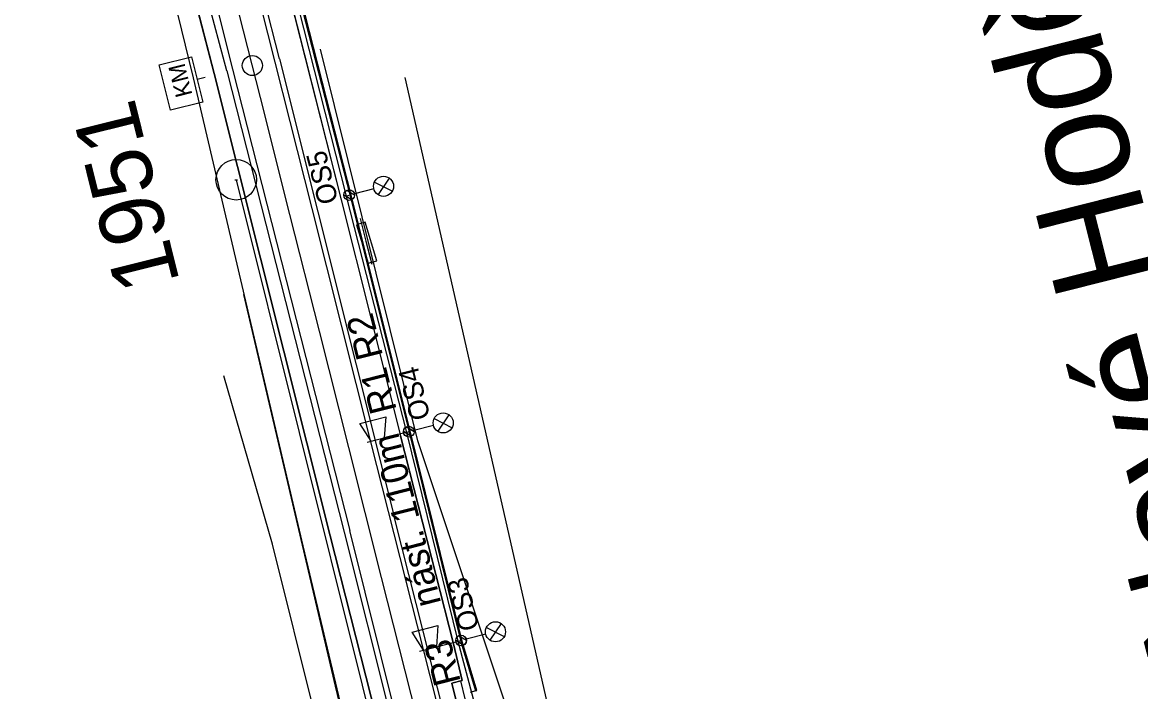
# Model space of a CAD drawing. Extents: x -754679 to -754173, y -1169241 to -1168288.
# Drawn here: x -754425.1 to -754341.7, y -1168914.1 to -1168864.2 of the extents above; entities that cross this region are included whole.
import ezdxf

# ---------------------------------------------------------------- set-up
doc = ezdxf.new("R2010")
doc.units = 0
for name, color, linetype in [('Vrstva 1', 7, 'Continuous'), ('Vrstva 14', 7, 'Continuous'), ('Vrstva 16', 7, 'Continuous'), ('Vrstva 2', 7, 'Continuous'), ('Vrstva 23', 7, 'Continuous'), ('Vrstva 25', 7, 'Continuous'), ('Vrstva 31', 7, 'Continuous'), ('Vrstva 33', 7, 'Continuous'), ('Vrstva 4', 7, 'Continuous'), ('Vrstva 43', 7, 'Continuous'), ('Vrstva 51', 7, 'Continuous'), ('Vrstva 53', 7, 'Continuous'), ('Vrstva 63', 7, 'Continuous'), ('Vrstva 7', 7, 'Continuous')]:
    doc.layers.add(name, color=color, linetype=linetype)

msp = doc.modelspace()

# ---------------------------------------------------------------- linework, layer by layer
at = {"layer": 'Vrstva 1'}
msp.add_line((-754409.148, -1168875.914), (-754409.148, -1168875.914), dxfattribs=at)
for points in [[(-754398.294, -1168905.574), (-754400.74, -1168895.891), (-754402.939, -1168887.198), (-754405.133, -1168878.507), (-754407.339, -1168869.778), (-754409.539, -1168861.07), (-754411.979, -1168851.401), (-754414.173, -1168842.726), (-754415.893, -1168835.935), (-754418.063, -1168827.345), (-754420.434, -1168817.966), (-754422.091, -1168811.412)], [(-754384.656, -1168959.571), (-754385.936, -1168954.491), (-754386.734, -1168951.322), (-754387.865, -1168946.893), (-754387.928, -1168946.598), (-754389.016, -1168942.293), (-754391.2, -1168933.67), (-754393.647, -1168923.979), (-754396.084, -1168914.315), (-754398.294, -1168905.574)]]:
    msp.add_lwpolyline(points, dxfattribs=at)
at = {"layer": 'Vrstva 14'}
for p, q in [((-754405.698, -1168860.083), (-754401.304, -1168877.422)), ((-754401.304, -1168877.422), (-754396.888, -1168895.004)), ((-754392.927, -1168910.532), (-754396.888, -1168895.004)), ((-754392.287, -1168913.272), (-754392.927, -1168910.532)), ((-754393.063, -1168913.475), (-754392.287, -1168913.272)), ((-754391.113, -1168921.242), (-754393.063, -1168913.475))]:
    msp.add_line(p, q, dxfattribs=at)
msp.add_lwpolyline([(-754414.276, -1168835.483), (-754412.566, -1168842.248), (-754407.917, -1168860.63), (-754403.513, -1168878.067), (-754399.115, -1168895.474), (-754395.207, -1168910.943), (-754391.772, -1168924.511), (-754387.375, -1168941.909)], dxfattribs=at)
at = {"layer": 'Vrstva 16'}
for p, q in [((-754412.329, -1168868.322), (-754417.897, -1168845.451)), ((-754410.781, -1168867.993), (-754402.14, -1168902.474)), ((-754404.14, -1168903.209), (-754412.329, -1168868.322)), ((-754402.14, -1168902.474), (-754395.222, -1168929.578)), ((-754397.82, -1168929.888), (-754404.14, -1168903.209))]:
    msp.add_line(p, q, dxfattribs=at)
msp.add_lwpolyline([(-754410.781, -1168867.993), (-754417.976, -1168840.388), (-754421.932, -1168825.961), (-754423.457, -1168821.011)], dxfattribs=at)
at = {"layer": 'Vrstva 23'}
for points in [[(-754381.681, -1168939.489), (-754386.122, -1168924.006), (-754387.953, -1168918.303), (-754395.607, -1168895.383), (-754402.869, -1168866.173)], [(-754399.909, -1168878.817), (-754399.485, -1168880.491), (-754399.03, -1168882.21)], [(-754393.344, -1168948.888), (-754397.546, -1168931.205), (-754401.742, -1168913.695), (-754408.583, -1168884.482)]]:
    msp.add_lwpolyline(points, dxfattribs=at)
msp.add_lwpolyline([(-754399.526, -1168879.083), (-754400.173, -1168879.277), (-754399.312, -1168882.147), (-754398.665, -1168881.952)], close=True, dxfattribs=at)
at = {"layer": 'Vrstva 25'}
for p, q in [((-754398.824, -1168876.083), (-754397.496, -1168876.762)), ((-754397.732, -1168875.791), (-754398.566, -1168877.027)), ((-754401.115, -1168877.031), (-754400.508, -1168877.393)), ((-754400.893, -1168876.698), (-754400.323, -1168877.038)), ((-754398.878, -1168876.59), (-754400.332, -1168876.958)), ((-754394.373, -1168893.733), (-754393.045, -1168894.412)), ((-754393.281, -1168893.442), (-754394.115, -1168894.678)), ((-754396.664, -1168894.682), (-754396.057, -1168895.044)), ((-754396.442, -1168894.349), (-754395.872, -1168894.689)), ((-754394.427, -1168894.241), (-754395.881, -1168894.609)), ((-754389.382, -1168909.02), (-754390.216, -1168910.256)), ((-754390.528, -1168909.819), (-754391.982, -1168910.187)), ((-754390.474, -1168909.312), (-754389.146, -1168909.991)), ((-754392.765, -1168910.26), (-754392.158, -1168910.622)), ((-754392.543, -1168909.927), (-754391.973, -1168910.267))]:
    msp.add_line(p, q, dxfattribs=at)
for points in [[(-754405.311, -1168859.885), (-754400.951, -1168877.139), (-754400.72, -1168877.056)], [(-754400.951, -1168877.139), (-754396.452, -1168894.774), (-754396.269, -1168894.707)], [(-754396.452, -1168894.774), (-754392.606, -1168910.34), (-754392.37, -1168910.285)], [(-754392.606, -1168910.34), (-754389.7, -1168921.276), (-754388.719, -1168923.201), (-754389.035, -1168923.735)]]:
    msp.add_lwpolyline(points, dxfattribs=at)
for centre, radius in [((-754398.153, -1168876.404), 0.749), ((-754400.72, -1168877.056), 0.4), ((-754393.702, -1168894.055), 0.749), ((-754396.269, -1168894.707), 0.4), ((-754389.803, -1168909.633), 0.749), ((-754392.37, -1168910.285), 0.4)]:
    msp.add_circle(centre, radius, dxfattribs=at)
at = {"layer": 'Vrstva 31'}
for points in [[(-754396.269, -1168894.707), (-754396.452, -1168894.774), (-754392.606, -1168910.34), (-754392.37, -1168910.285)], [(-754392.606, -1168910.34), (-754389.7, -1168921.276), (-754388.719, -1168923.201), (-754389.035, -1168923.735)]]:
    msp.add_lwpolyline(points, dxfattribs=at)
at = {"layer": 'Vrstva 33'}
for p, q in [((-754399.367, -1168895.491), (-754396.657, -1168894.805)), ((-754396.068, -1168895.052), (-754396.666, -1168894.696)), ((-754395.871, -1168894.704), (-754396.456, -1168894.355)), ((-754395.469, -1168911.068), (-754392.758, -1168910.383)), ((-754392.169, -1168910.63), (-754392.767, -1168910.274)), ((-754391.972, -1168910.282), (-754392.557, -1168909.933))]:
    msp.add_line(p, q, dxfattribs=at)
for points in [[(-754399.077, -1168895.417), (-754399.929, -1168894.086), (-754397.99, -1168893.595), (-754398.107, -1168895.172)], [(-754395.178, -1168910.995), (-754396.03, -1168909.663), (-754394.091, -1168909.173), (-754394.208, -1168910.75)]]:
    msp.add_lwpolyline(points, dxfattribs=at)
for centre in [(-754396.269, -1168894.707), (-754392.37, -1168910.285)]:
    msp.add_circle(centre, 0.401, dxfattribs=at)
at = {"layer": 'Vrstva 4'}
for p, q in [((-754409.837, -1168867.801), (-754424.763, -1168812.141)), ((-754423.571, -1168811.713), (-754409.415, -1168867.665)), ((-754425.102, -1168812.48), (-754410.781, -1168867.993)), ((-754405.916, -1168866.884), (-754414.18, -1168834.25)), ((-754405.916, -1168866.884), (-754397.327, -1168901.139)), ((-754402.14, -1168902.474), (-754410.781, -1168867.993)), ((-754409.837, -1168867.801), (-754401.081, -1168902.211)), ((-754409.415, -1168867.665), (-754400.667, -1168902.072)), ((-754390.328, -1168928.8), (-754397.327, -1168901.139)), ((-754401.081, -1168902.211), (-754394.179, -1168929.708)), ((-754393.809, -1168929.698), (-754400.667, -1168902.072)), ((-754395.222, -1168929.578), (-754402.14, -1168902.474))]:
    msp.add_line(p, q, dxfattribs=at)
at = {"layer": 'Vrstva 43'}
msp.add_line((-754392.405, -1168913.302), (-754391.226, -1168918.175), dxfattribs=at)
at = {"layer": 'Vrstva 51'}
for p, q in [((-754405.058, -1168859.927), (-754400.625, -1168877.238)), ((-754400.518, -1168877.236), (-754404.921, -1168859.923)), ((-754400.625, -1168877.238), (-754396.226, -1168894.847)), ((-754396.119, -1168894.852), (-754400.518, -1168877.236)), ((-754396.226, -1168894.847), (-754392.355, -1168910.448)), ((-754392.262, -1168910.44), (-754396.119, -1168894.852)), ((-754392.355, -1168910.448), (-754391.3, -1168914.039)), ((-754391.199, -1168914.018), (-754392.262, -1168910.44)), ((-754391.3, -1168914.039), (-754391.701, -1168914.153)), ((-754391.3, -1168914.039), (-754391.199, -1168914.018))]:
    msp.add_line(p, q, dxfattribs=at)
msp.add_lwpolyline([(-754412.047, -1168834.907), (-754410.208, -1168842.187), (-754405.698, -1168860.083), (-754401.304, -1168877.422), (-754396.888, -1168895.004), (-754392.927, -1168910.532), (-754392.287, -1168913.272), (-754393.063, -1168913.475), (-754391.113, -1168921.242), (-754390.299, -1168921.015), (-754389.528, -1168924.038), (-754385.162, -1168941.315)], dxfattribs=at)
at = {"layer": 'Vrstva 53'}
for p, q in [((-754396.56, -1168868.29), (-754379.05, -1168945.33)), ((-754406.43, -1168903.09), (-754410.06, -1168890.53)), ((-754396.05, -1168944.82), (-754406.43, -1168903.09))]:
    msp.add_line(p, q, dxfattribs=at)
at = {"layer": 'Vrstva 63'}
msp.add_line((-754409.248, -1168875.914), (-754409.048, -1168875.914), dxfattribs=at)
msp.add_lwpolyline([(-754409.148, -1168875.914), (-754380.947, -1168989.007), (-754335.988, -1169164.84)], dxfattribs=at)
msp.add_circle((-754409.148, -1168875.914), 1.512, dxfattribs=at)
at = {"layer": 'Vrstva 7'}
msp.add_line((-754411.454, -1168868.282), (-754412.058, -1168868.435), dxfattribs=at)
msp.add_lwpolyline([(-754411.631, -1168870.124), (-754414.039, -1168870.732), (-754414.893, -1168867.35), (-754412.486, -1168866.742)], close=True, dxfattribs=at)
msp.add_circle((-754407.941, -1168867.395), 0.75, dxfattribs=at)

# ---------------------------------------------------------------- texts
at = {"layer": 'Vrstva 14'}
msp.add_text('nást. 110m', height=2, rotation=104.17821, dxfattribs=at).set_placement((-754393.844, -1168907.498))
at = {"layer": 'Vrstva 2'}
msp.add_text('1951', height=4.8, rotation=104.00179, dxfattribs=at).set_placement((-754413.336, -1168883.555))
at = {"layer": 'Vrstva 23'}
msp.add_text('zast. Nové Hodějovice', height=8, rotation=104.17859, dxfattribs=at).set_placement((-754326.915, -1168935.19))
at = {"layer": 'Vrstva 25'}
for s, rotation, p in [('OS5', 104.16802, (-754401.518, -1168877.525)), ('OS4', 104.17678, (-754394.646, -1168893.635)), ('OS3', 104.18883, (-754390.989, -1168909.35))]:
    msp.add_text(s, height=1.5, rotation=rotation, dxfattribs=at).set_placement(p)
at = {"layer": 'Vrstva 33'}
for s, rotation, p in [('R1 R2', 104.19587, (-754397.154, -1168893.084)), ('R3', 104.18883, (-754392.378, -1168913.363))]:
    msp.add_text(s, height=2, rotation=rotation, dxfattribs=at).set_placement(p)
at = {"layer": 'Vrstva 7'}
msp.add_text('KM', height=1.2469, rotation=104.17859, dxfattribs=at).set_placement((-754412.409, -1168869.572))

doc.saveas('drawing.dxf')
